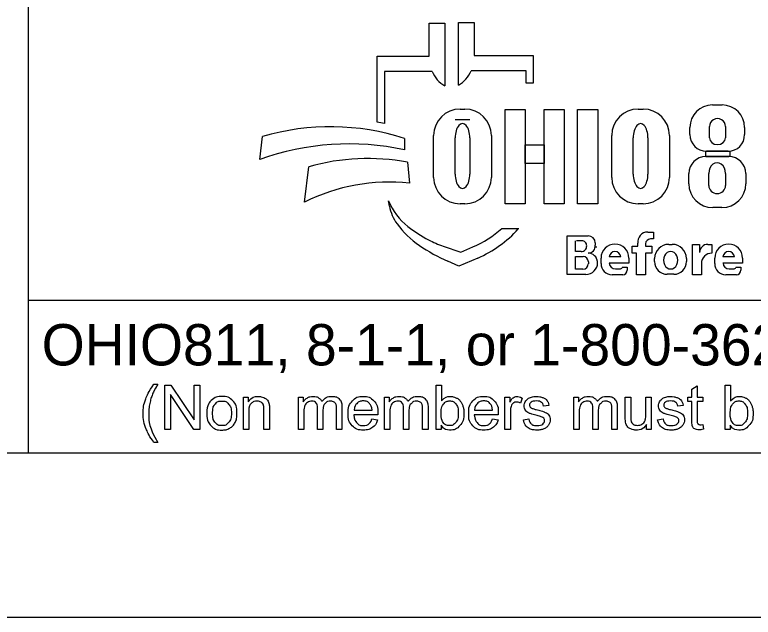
# Model space of a CAD drawing. Extents: x 0 to 34, y 0 to 22.
# Drawn here: x 2.043 to 4.294, y 0 to 1.837 of the extents above; entities that cross this region are included whole.
import ezdxf

# ---------------------------------------------------------------- set-up
doc = ezdxf.new("R2010")
doc.units = 0
for name, color, linetype in [('SH_Border', 7, 'Continuous'), ('SH_Cut_Line', 7, 'Continuous'), ('SH_Data', 7, 'Continuous'), ('SH_Text', 7, 'Continuous')]:
    doc.layers.add(name, color=color, linetype=linetype)

msp = doc.modelspace()

# ---------------------------------------------------------------- linework, layer by layer
at = {"layer": 'SH_Border'}
msp.add_lwpolyline([(1.5, 21.5), (33.5, 21.5), (33.5, 0.5), (1.5, 0.5)], close=True, dxfattribs=at)
at = {"layer": 'SH_Cut_Line'}
msp.add_lwpolyline([(0, 0), (34, 0), (34, 22), (0, 22)], close=True, dxfattribs=at)
at = {"layer": 'SH_Data'}
for p, q in [((2.0853, 0.5), (2.0853, 2.6037)), ((5.9103, 0.9661), (2.0853, 0.9661)), ((5.9103, 0.5), (2.0853, 0.5))]:
    msp.add_line(p, q, dxfattribs=at)
at = {"layer": 'SH_Text'}
for p, q in [((3.3057, 1.711), (3.3057, 1.8113)), ((3.3057, 1.8113), (3.354, 1.8113)), ((3.354, 1.8113), (3.354, 1.6204)), ((3.3951, 1.6225), (3.3951, 1.8134)), ((3.3951, 1.8134), (3.4433, 1.8134)), ((3.4433, 1.8134), (3.4433, 1.713)), ((3.1473, 1.5095), (3.1473, 1.711)), ((3.1473, 1.711), (3.3057, 1.711)), ((3.4433, 1.713), (3.6227, 1.713)), ((3.6227, 1.713), (3.6227, 1.6286)), ((3.6017, 1.6667), (3.434, 1.6667)), ((3.6017, 1.6286), (3.6017, 1.6667)), ((3.1701, 1.6647), (3.1701, 1.5055)), ((3.3151, 1.6647), (3.1701, 1.6647)), ((3.6227, 1.6286), (3.6017, 1.6286)), ((4.1693, 1.5623), (4.1988, 1.5623)), ((3.4002, 1.5497), (3.4151, 1.5497)), ((3.9429, 1.5497), (3.9578, 1.5497)), ((3.4301, 1.5164), (3.3853, 1.5164)), ((4.1006, 1.4717), (4.1006, 1.4936)), ((4.1602, 1.4615), (4.1602, 1.4969)), ((4.2089, 1.4969), (4.2089, 1.4615)), ((4.2675, 1.4936), (4.2675, 1.4717)), ((2.7897, 1.3958), (2.7982, 1.4661)), ((3.3197, 1.3414), (3.3197, 1.4692)), ((3.4956, 1.4692), (3.4956, 1.3414)), ((3.8624, 1.3414), (3.8624, 1.4692)), ((4.0383, 1.4692), (4.0383, 1.3414)), ((3.2313, 1.4603), (3.2313, 1.4253)), ((3.3853, 1.3516), (3.3853, 1.4617)), ((3.4301, 1.4617), (3.4301, 1.3516)), ((3.928, 1.3516), (3.928, 1.4617)), ((3.9728, 1.4617), (3.9728, 1.3516)), ((4.2171, 1.4213), (4.151, 1.4213)), ((4.1494, 1.4049), (4.219, 1.4049)), ((2.9264, 1.2657), (2.9396, 1.3738)), ((3.2403, 1.3877), (3.2459, 1.3239)), ((4.0973, 1.3221), (4.0973, 1.3528)), ((4.158, 1.3168), (4.158, 1.3536)), ((4.2092, 1.3536), (4.2092, 1.3168)), ((4.2711, 1.3528), (4.2711, 1.3221)), ((3.1853, 1.2541), (3.1825, 1.2702)), ((3.4151, 1.2608), (3.4002, 1.2608)), ((3.9578, 1.2608), (3.9429, 1.2608)), ((4.1982, 1.2493), (4.1702, 1.2493)), ((3.5275, 1.1858), (3.5792, 1.1858)), ((3.972, 1.1748), (3.9895, 1.1748)), ((3.9895, 1.1748), (3.9895, 1.1541)), ((3.7267, 1.0456), (3.7267, 1.1633)), ((3.7267, 1.1633), (3.7908, 1.1633)), ((3.7519, 1.1152), (3.7519, 1.1484)), ((3.7746, 1.1484), (3.7554, 1.1484)), ((3.9895, 1.1537), (3.9804, 1.1537)), ((3.3489, 1.1315), (3.4024, 1.113)), ((3.4024, 1.113), (3.4394, 1.1291)), ((3.8121, 1.1419), (3.8121, 1.1348)), ((3.9247, 1.1106), (3.9247, 1.1312)), ((3.9247, 1.1312), (3.9421, 1.1312)), ((3.9421, 1.1312), (3.9421, 1.1407)), ((3.9656, 1.1388), (3.9656, 1.1312)), ((3.9656, 1.1312), (3.985, 1.1312)), ((3.985, 1.1312), (3.985, 1.1106)), ((4.0361, 1.1372), (4.047, 1.1372)), ((4.1083, 1.0446), (4.1083, 1.137)), ((4.1083, 1.137), (4.1304, 1.137)), ((4.1304, 1.137), (4.1304, 1.1128)), ((4.155, 1.137), (4.1675, 1.137)), ((4.1675, 1.137), (4.1675, 1.1103)), ((3.7694, 1.1152), (3.7519, 1.1152)), ((3.9381, 1.1106), (3.9247, 1.1106)), ((3.9381, 1.0446), (3.9381, 1.1106)), ((3.985, 1.1106), (3.9656, 1.1106)), ((3.9656, 1.1106), (3.9656, 1.0446)), ((3.397, 1.0707), (3.3634, 1.0855)), ((3.454, 1.0954), (3.397, 1.0707)), ((3.7519, 1.0617), (3.7519, 1.1003)), ((3.7519, 1.1003), (3.7749, 1.1003)), ((3.7912, 1.0839), (3.7912, 1.0782)), ((3.8194, 1.0813), (3.8194, 1.081)), ((3.8298, 1.0787), (3.8298, 1.0953)), ((3.8897, 1.0989), (3.855, 1.0989)), ((3.9149, 1.0953), (3.9149, 1.0794)), ((3.9931, 1.0844), (3.9931, 1.0941)), ((4.0901, 1.0941), (4.0901, 1.0844)), ((4.1762, 1.0787), (4.1762, 1.0953)), ((4.2361, 1.0989), (4.2015, 1.0989)), ((4.2613, 1.0953), (4.2613, 1.0794)), ((3.7746, 1.0617), (3.7519, 1.0617)), ((3.9149, 1.0794), (3.8551, 1.0794)), ((3.8739, 1.0621), (3.8866, 1.0621)), ((3.8943, 1.0671), (3.9095, 1.0671)), ((3.9095, 1.0671), (3.9095, 1.0583)), ((4.1358, 1.0789), (4.1358, 1.0446)), ((4.2613, 1.0794), (4.2015, 1.0794)), ((4.2204, 1.0621), (4.2331, 1.0621)), ((4.2408, 1.0671), (4.256, 1.0671)), ((4.256, 1.0671), (4.256, 1.0583)), ((3.784, 1.0456), (3.7267, 1.0456)), ((3.8958, 1.0446), (3.864, 1.0446)), ((3.9656, 1.0446), (3.9381, 1.0446)), ((4.0516, 1.0459), (4.0316, 1.0459)), ((4.1358, 1.0446), (4.1083, 1.0446)), ((4.2423, 1.0446), (4.2104, 1.0446))]:
    msp.add_line(p, q, dxfattribs=at)
for points in [[(3.5374, 1.5487), (3.5985, 1.5487), (3.5985, 1.2608), (3.5374, 1.2608)], [(3.6563, 1.5487), (3.7175, 1.5487), (3.7175, 1.2608), (3.6563, 1.2608)], [(3.7583, 1.5487), (3.8202, 1.5487), (3.8202, 1.2608), (3.7583, 1.2608)], [(3.5985, 1.4408), (3.6563, 1.4408), (3.6563, 1.3833), (3.5985, 1.3833)], [(4.1491, 1.4214), (4.2226, 1.4214), (4.2226, 1.4047), (4.1491, 1.4047)]]:
    msp.add_lwpolyline(points, close=True, dxfattribs=at)
for points in [[(2.4674, 0.7104), (2.4793, 0.7104)], [(2.5005, 0.573), (2.5005, 0.7082), (2.5188, 0.7082), (2.5899, 0.602), (2.5899, 0.7082), (2.607, 0.7082), (2.607, 0.573), (2.5887, 0.573), (2.5176, 0.6792), (2.5176, 0.573), (2.5005, 0.573)], [(3.3424, 0.573), (3.3271, 0.573), (3.3271, 0.7082), (3.3436, 0.7082), (3.3436, 0.66)], [(4.1065, 0.6017), (4.1065, 0.6581), (4.0942, 0.6581), (4.0942, 0.671), (4.1065, 0.671), (4.1065, 0.6952), (4.123, 0.7052), (4.123, 0.671), (4.1396, 0.671), (4.1396, 0.6581), (4.123, 0.6581), (4.123, 0.6007)], [(4.2236, 0.573), (4.2082, 0.573), (4.2082, 0.7082), (4.2248, 0.7082), (4.2248, 0.66)], [(2.7399, 0.573), (2.7399, 0.671), (2.7548, 0.671), (2.7548, 0.6571)], [(2.9076, 0.573), (2.9076, 0.671), (2.9225, 0.671), (2.9225, 0.6571)], [(3.1699, 0.573), (3.1699, 0.671), (3.1847, 0.671), (3.1847, 0.6571)], [(3.5369, 0.573), (3.5369, 0.671), (3.5518, 0.671), (3.5518, 0.6561)], [(3.59, 0.6678), (3.5842, 0.6525)], [(3.7468, 0.573), (3.7468, 0.671), (3.7616, 0.671), (3.7616, 0.6571)], [(3.9037, 0.6103), (3.9037, 0.671), (3.9202, 0.671), (3.9202, 0.6167)], [(3.9664, 0.6185), (3.9664, 0.671), (3.983, 0.671), (3.983, 0.573), (3.9681, 0.573)], [(2.8194, 0.6332), (2.8194, 0.573), (2.8028, 0.573), (2.8028, 0.6325)], [(2.9824, 0.6299), (2.9824, 0.573), (2.9658, 0.573), (2.9658, 0.6366)], [(3.0404, 0.6402), (3.0404, 0.573), (3.0238, 0.573), (3.0238, 0.6347)], [(3.0774, 0.6313), (3.1321, 0.6313)], [(3.2446, 0.6299), (3.2446, 0.573), (3.2281, 0.573), (3.2281, 0.6366)], [(3.3026, 0.6402), (3.3026, 0.573), (3.2861, 0.573), (3.2861, 0.6347)], [(3.4446, 0.6313), (3.4993, 0.6313)], [(3.671, 0.6456), (3.6547, 0.6435)], [(3.8215, 0.6299), (3.8215, 0.573), (3.805, 0.573), (3.805, 0.6366)], [(3.8795, 0.6402), (3.8795, 0.573), (3.863, 0.573), (3.863, 0.6347)], [(4.0801, 0.6456), (4.0638, 0.6435)], [(2.7564, 0.6265), (2.7564, 0.573), (2.7399, 0.573)], [(2.9242, 0.6238), (2.9242, 0.573), (2.9076, 0.573)], [(3.1495, 0.6177), (3.0765, 0.6177)], [(3.1865, 0.6238), (3.1865, 0.573), (3.1699, 0.573)], [(3.5167, 0.6177), (3.4437, 0.6177)], [(3.5535, 0.6243), (3.5535, 0.573), (3.5369, 0.573)], [(3.7634, 0.6238), (3.7634, 0.573), (3.7468, 0.573)], [(3.1319, 0.6046), (3.149, 0.6025)], [(3.3424, 0.5853), (3.3424, 0.573)], [(3.4991, 0.6046), (3.5162, 0.6025)], [(3.5932, 0.6023), (3.6096, 0.6048)], [(3.9681, 0.573), (3.9681, 0.5875)], [(4.0023, 0.6023), (4.0187, 0.6048)], [(4.1396, 0.5878), (4.142, 0.5732)], [(4.2236, 0.5853), (4.2236, 0.573)], [(2.4793, 0.5333), (2.4674, 0.5333)]]:
    msp.add_lwpolyline(points, dxfattribs=at)
for centre, radius, start, end in [((3.3518, 1.6998), 0.0886, 299.2531, 338.0704), ((3.3973, 1.6978), 0.0886, 201.9296, 240.7469), ((4.1693, 1.4936), 0.0687, 90, 180), ((4.1988, 1.4936), 0.0687, 0, 90), ((3.4002, 1.4692), 0.0805, 90, 180), ((3.4151, 1.4692), 0.0805, 0, 90), ((3.9429, 1.4692), 0.0805, 90, 180), ((3.9578, 1.4692), 0.0805, 0, 90), ((3.032, 0.7814), 0.7372, 79.2074, 81.0007), ((3.0052, 0.7586), 0.7372, 72.1402, 106.3144), ((4.151, 1.4717), 0.0504, 180, 270), ((4.2171, 1.4717), 0.0504, 270, 0), ((3.062, 0.6406), 0.8027, 77.8238, 109.8274), ((3.1195, 0.7399), 0.659, 79.44, 105.8467), ((4.1494, 1.3528), 0.0521, 90, 180), ((4.219, 1.3528), 0.0521, 0, 90), ((3.4002, 1.3414), 0.0805, 180, 270), ((3.4151, 1.3414), 0.0805, 270, 0), ((3.9429, 1.3414), 0.0805, 180, 270), ((3.9578, 1.3414), 0.0805, 270, 0), ((3.1843, 0.755), 0.5721, 83.8248, 116.8021), ((4.1702, 1.3221), 0.0729, 180, 270), ((4.1982, 1.3221), 0.0729, 270, 0), ((3.3512, 1.3351), 0.1807, 201.0457, 232.5314), ((3.3124, 1.2758), 0.129, 189.6817, 216.0884), ((3.4328, 1.3635), 0.2779, 216.0884, 235.7167), ((3.5245, 1.5612), 0.4656, 232.5314, 241.794), ((3.3103, 1.4265), 0.3242, 293.4582, 312.0712), ((3.3103, 1.4265), 0.3609, 293.4582, 317.8286), ((3.972, 1.1446), 0.0302, 90, 187.5187), ((3.4478, 1.4183), 0.3034, 241.794, 250.9821), ((3.771, 1.1332), 0.0152, 357.8325, 90), ((3.7908, 1.1419), 0.0214, 0, 90), ((3.9804, 1.1388), 0.0148, 90, 180), ((3.5826, 1.5833), 0.5439, 235.7167, 246.2325), ((3.7694, 1.132), 0.0169, 270, 2.0582), ((3.7904, 1.1323), 0.0219, 270, 6.6529), ((3.7999, 1.1309), 0.0158, 347.4023, 0), ((3.8723, 1.0953), 0.0425, 0, 180), ((4.0361, 1.0941), 0.043, 90, 180), ((4.047, 1.0941), 0.043, 0, 90), ((4.1546, 1.1128), 0.0242, 89.2449, 180), ((4.2188, 1.0953), 0.0425, 0, 180), ((3.7905, 1.0815), 0.0289, 4.0748, 90), ((3.8724, 1.098), 0.0174, 2.9632, 177.0368), ((4.1672, 1.0789), 0.0314, 89.6033, 180), ((4.2188, 1.098), 0.0174, 2.9632, 177.0368), ((3.7749, 1.0839), 0.0163, 0, 90), ((3.784, 1.081), 0.0354, 270, 0), ((3.7897, 1.0813), 0.0297, 0, 11.7502), ((4.0316, 1.0844), 0.0385, 180, 270), ((4.0516, 1.0844), 0.0385, 270, 0), ((3.7746, 1.0782), 0.0165, 270, 0), ((3.864, 1.0787), 0.0342, 180, 270), ((3.8739, 1.081), 0.0189, 184.827, 270), ((3.8866, 1.0705), 0.00845, 270, 335.9979), ((3.8958, 1.0583), 0.0137, 270, 0), ((4.2104, 1.0787), 0.0342, 180, 270), ((4.2204, 1.081), 0.0189, 184.827, 270), ((4.2331, 1.0705), 0.00845, 270, 335.9979), ((4.2423, 1.0583), 0.0137, 270, 0)]:
    msp.add_arc(centre, radius, start, end, dxfattribs=at)
for centre, major_axis, ratio, start_param, end_param in [((4.1845, 1.4969), (0.0244, 0), 0.969373, 0, 3.141593), ((3.4077, 1.4617), (0, 0.0436), 0.514403, 4.712389, 7.853982), ((3.9504, 1.4617), (0, 0.0436), 0.514403, 4.712389, 7.853982), ((4.1845, 1.4615), (0.0244, 0), 0.818453, 3.141593, 6.283185), ((4.1836, 1.3536), (0, 0.0322), 0.794529, 4.712389, 7.853982), ((3.4077, 1.3516), (0, 0.0436), 0.514403, 1.570796, 4.712389), ((3.9504, 1.3516), (0, 0.0436), 0.514403, 1.570796, 4.712389), ((4.1836, 1.3168), (0.0256, 0), 0.959837, 3.141593, 6.283185), ((4.042, 1.0893), (0, 0.0261), 0.832186, 4.712389, 7.853982), ((4.042, 1.0893), (0, 0.0272), 0.797287, 1.570796, 4.712389)]:
    msp.add_ellipse(centre, major_axis=major_axis, ratio=ratio, start_param=start_param, end_param=end_param, dxfattribs=at)
for points in [[(2.4674, 0.5333), (2.4537, 0.5506), (2.4442, 0.5738), (2.4347, 0.597), (2.4347, 0.6219), (2.4347, 0.6439), (2.4418, 0.664), (2.4501, 0.6873), (2.4674, 0.7104)], [(2.4793, 0.7104), (2.4681, 0.6912), (2.4646, 0.683), (2.459, 0.6703), (2.4557, 0.6565), (2.4518, 0.6393), (2.4518, 0.6218), (2.4518, 0.5775), (2.4793, 0.5333)], [(2.6287, 0.622), (2.6287, 0.6492), (2.6438, 0.6623), (2.6565, 0.6731), (2.6746, 0.6731), (2.6948, 0.6731), (2.7076, 0.6599), (2.7204, 0.6467), (2.7204, 0.6234), (2.7204, 0.6045), (2.7147, 0.5937), (2.7091, 0.5828), (2.6982, 0.5768), (2.6874, 0.5709), (2.6746, 0.5709), (2.6541, 0.5709), (2.6414, 0.584), (2.6287, 0.5972), (2.6287, 0.622)], [(2.6458, 0.622), (2.6458, 0.6032), (2.654, 0.5938), (2.6622, 0.5845), (2.6746, 0.5845), (2.6869, 0.5845), (2.6951, 0.5939), (2.7033, 0.6033), (2.7033, 0.6225), (2.7033, 0.6407), (2.6951, 0.6501), (2.6868, 0.6594), (2.6746, 0.6594), (2.6622, 0.6594), (2.654, 0.6501), (2.6458, 0.6408), (2.6458, 0.622)], [(2.7548, 0.6571), (2.7656, 0.6731), (2.7859, 0.6731), (2.7948, 0.6731), (2.8022, 0.67), (2.8096, 0.6668), (2.8133, 0.6616), (2.817, 0.6564), (2.8185, 0.6493), (2.8194, 0.6447), (2.8194, 0.6332)], [(2.8028, 0.6325), (2.8028, 0.6427), (2.8009, 0.6477), (2.7989, 0.6527), (2.794, 0.6557), (2.7891, 0.6587), (2.7824, 0.6587), (2.7718, 0.6587), (2.7641, 0.652), (2.7564, 0.6453), (2.7564, 0.6265)], [(2.9225, 0.6571), (2.9271, 0.6644), (2.9347, 0.6687), (2.9424, 0.6731), (2.9522, 0.6731), (2.963, 0.6731), (2.97, 0.6686), (2.977, 0.6641), (2.9798, 0.6559), (2.9915, 0.6731), (3.0101, 0.6731), (3.0247, 0.6731), (3.0326, 0.6651), (3.0404, 0.657), (3.0404, 0.6402)], [(2.9658, 0.6366), (2.9658, 0.6477), (2.9618, 0.6532), (2.9577, 0.6587), (2.9485, 0.6587), (2.9415, 0.6587), (2.9355, 0.655), (2.9296, 0.6513), (2.9269, 0.6442), (2.9242, 0.6372), (2.9242, 0.6238)], [(3.0238, 0.6347), (3.0238, 0.6446), (3.0222, 0.649), (3.0206, 0.6534), (3.0163, 0.656), (3.0121, 0.6587), (3.0064, 0.6587), (2.9961, 0.6587), (2.9892, 0.6518), (2.9824, 0.645), (2.9824, 0.6299)], [(3.149, 0.6025), (3.145, 0.5874), (3.134, 0.5792), (3.1231, 0.5709), (3.106, 0.5709), (3.0845, 0.5709), (3.0719, 0.5841), (3.0594, 0.5973), (3.0594, 0.6212), (3.0594, 0.6459), (3.0721, 0.6595), (3.0848, 0.6731), (3.1051, 0.6731), (3.1247, 0.6731), (3.1372, 0.6598), (3.1496, 0.6464), (3.1496, 0.6221), (3.1496, 0.6207), (3.1495, 0.6177)], [(3.1321, 0.6313), (3.131, 0.6437), (3.1258, 0.6499), (3.1179, 0.6595), (3.1052, 0.6595), (3.0938, 0.6595), (3.086, 0.6519), (3.0782, 0.6442), (3.0774, 0.6313)], [(3.1847, 0.6571), (3.1893, 0.6644), (3.197, 0.6687), (3.2046, 0.6731), (3.2144, 0.6731), (3.2253, 0.6731), (3.2322, 0.6686), (3.2392, 0.6641), (3.2421, 0.6559), (3.2537, 0.6731), (3.2724, 0.6731), (3.2869, 0.6731), (3.2948, 0.6651), (3.3026, 0.657), (3.3026, 0.6402)], [(3.2281, 0.6366), (3.2281, 0.6477), (3.224, 0.6532), (3.2199, 0.6587), (3.2107, 0.6587), (3.2037, 0.6587), (3.1978, 0.655), (3.1918, 0.6513), (3.1891, 0.6442), (3.1865, 0.6372), (3.1865, 0.6238)], [(3.2861, 0.6347), (3.2861, 0.6446), (3.2844, 0.649), (3.2828, 0.6534), (3.2786, 0.656), (3.2743, 0.6587), (3.2686, 0.6587), (3.2583, 0.6587), (3.2515, 0.6518), (3.2446, 0.645), (3.2446, 0.6299)], [(3.3422, 0.6227), (3.3422, 0.6051), (3.347, 0.5973), (3.3548, 0.5845), (3.3682, 0.5845), (3.379, 0.5845), (3.3869, 0.5939), (3.3948, 0.6034), (3.3948, 0.6221), (3.3948, 0.6413), (3.3872, 0.6504), (3.3797, 0.6595), (3.3689, 0.6595), (3.358, 0.6595), (3.3501, 0.6501), (3.3422, 0.6406), (3.3422, 0.6227)], [(3.3436, 0.66), (3.3542, 0.6731), (3.3705, 0.6731), (3.3795, 0.6731), (3.3876, 0.6695), (3.3956, 0.6659), (3.4008, 0.6593), (3.406, 0.6527), (3.409, 0.6434), (3.4119, 0.6341), (3.4119, 0.6235), (3.4119, 0.5983), (3.3995, 0.5846), (3.387, 0.5709), (3.3696, 0.5709), (3.3523, 0.5709), (3.3424, 0.5853)], [(3.5162, 0.6025), (3.5122, 0.5874), (3.5012, 0.5792), (3.4902, 0.5709), (3.4732, 0.5709), (3.4517, 0.5709), (3.4391, 0.5841), (3.4266, 0.5973), (3.4266, 0.6212), (3.4266, 0.6459), (3.4393, 0.6595), (3.452, 0.6731), (3.4723, 0.6731), (3.4919, 0.6731), (3.5043, 0.6598), (3.5168, 0.6464), (3.5168, 0.6221), (3.5168, 0.6207), (3.5167, 0.6177)], [(3.4993, 0.6313), (3.4982, 0.6437), (3.493, 0.6499), (3.4851, 0.6595), (3.4724, 0.6595), (3.461, 0.6595), (3.4532, 0.6519), (3.4454, 0.6442), (3.4446, 0.6313)], [(3.5518, 0.6561), (3.5575, 0.6665), (3.5624, 0.6698), (3.5672, 0.6731), (3.573, 0.6731), (3.5814, 0.6731), (3.59, 0.6678)], [(3.5842, 0.6525), (3.5782, 0.656), (3.5721, 0.656), (3.5667, 0.656), (3.5624, 0.6528), (3.5581, 0.6495), (3.5562, 0.6437), (3.5535, 0.6348), (3.5535, 0.6243)], [(3.6547, 0.6435), (3.6536, 0.651), (3.6483, 0.6553), (3.643, 0.6595), (3.6333, 0.6595), (3.6218, 0.6595), (3.617, 0.6558), (3.6121, 0.652), (3.6121, 0.6469), (3.6121, 0.6437), (3.6141, 0.6411), (3.6161, 0.6384), (3.6205, 0.6366), (3.623, 0.6357), (3.6351, 0.6324), (3.6528, 0.6277), (3.6598, 0.6247), (3.6667, 0.6217), (3.6707, 0.616), (3.6747, 0.6103), (3.6747, 0.6018), (3.6747, 0.5935), (3.6698, 0.5862), (3.665, 0.5789), (3.6558, 0.5749), (3.6467, 0.5709), (3.6352, 0.5709), (3.616, 0.5709), (3.606, 0.5788), (3.596, 0.5867), (3.5932, 0.6023)], [(3.6096, 0.6048), (3.611, 0.595), (3.6173, 0.5897), (3.6236, 0.5845), (3.635, 0.5845), (3.6465, 0.5845), (3.652, 0.5891), (3.6576, 0.5938), (3.6576, 0.6001), (3.6576, 0.6057), (3.6527, 0.6089), (3.6493, 0.6111), (3.6357, 0.6146), (3.6174, 0.6192), (3.6104, 0.6225), (3.6033, 0.6259), (3.5996, 0.6318), (3.596, 0.6378), (3.596, 0.6449), (3.596, 0.6515), (3.599, 0.6571), (3.602, 0.6626), (3.6072, 0.6663), (3.611, 0.6692), (3.6177, 0.6712), (3.6244, 0.6731), (3.6321, 0.6731), (3.6436, 0.6731), (3.6524, 0.6698), (3.6611, 0.6665), (3.6653, 0.6608), (3.6694, 0.6551), (3.671, 0.6456)], [(3.7616, 0.6571), (3.7662, 0.6644), (3.7739, 0.6687), (3.7815, 0.6731), (3.7913, 0.6731), (3.8022, 0.6731), (3.8091, 0.6686), (3.8161, 0.6641), (3.819, 0.6559), (3.8306, 0.6731), (3.8492, 0.6731), (3.8638, 0.6731), (3.8717, 0.6651), (3.8795, 0.657), (3.8795, 0.6402)], [(3.805, 0.6366), (3.805, 0.6477), (3.8009, 0.6532), (3.7968, 0.6587), (3.7876, 0.6587), (3.7806, 0.6587), (3.7747, 0.655), (3.7687, 0.6513), (3.766, 0.6442), (3.7634, 0.6372), (3.7634, 0.6238)], [(3.863, 0.6347), (3.863, 0.6446), (3.8613, 0.649), (3.8597, 0.6534), (3.8555, 0.656), (3.8512, 0.6587), (3.8455, 0.6587), (3.8352, 0.6587), (3.8284, 0.6518), (3.8215, 0.645), (3.8215, 0.6299)], [(4.0638, 0.6435), (4.0627, 0.651), (4.0574, 0.6553), (4.0521, 0.6595), (4.0424, 0.6595), (4.031, 0.6595), (4.0261, 0.6558), (4.0212, 0.652), (4.0212, 0.6469), (4.0212, 0.6437), (4.0232, 0.6411), (4.0252, 0.6384), (4.0296, 0.6366), (4.0321, 0.6357), (4.0443, 0.6324), (4.0619, 0.6277), (4.0689, 0.6247), (4.0758, 0.6217), (4.0798, 0.616), (4.0838, 0.6103), (4.0838, 0.6018), (4.0838, 0.5935), (4.0789, 0.5862), (4.0741, 0.5789), (4.065, 0.5749), (4.0558, 0.5709), (4.0443, 0.5709), (4.0251, 0.5709), (4.0151, 0.5788), (4.0051, 0.5867), (4.0023, 0.6023)], [(4.0187, 0.6048), (4.0201, 0.595), (4.0264, 0.5897), (4.0328, 0.5845), (4.0441, 0.5845), (4.0556, 0.5845), (4.0612, 0.5891), (4.0667, 0.5938), (4.0667, 0.6001), (4.0667, 0.6057), (4.0618, 0.6089), (4.0584, 0.6111), (4.0448, 0.6146), (4.0265, 0.6192), (4.0195, 0.6225), (4.0124, 0.6259), (4.0088, 0.6318), (4.0051, 0.6378), (4.0051, 0.6449), (4.0051, 0.6515), (4.0081, 0.6571), (4.0111, 0.6626), (4.0163, 0.6663), (4.0202, 0.6692), (4.0269, 0.6712), (4.0336, 0.6731), (4.0412, 0.6731), (4.0528, 0.6731), (4.0615, 0.6698), (4.0702, 0.6665), (4.0744, 0.6608), (4.0785, 0.6551), (4.0801, 0.6456)], [(4.2234, 0.6227), (4.2234, 0.6051), (4.2281, 0.5973), (4.236, 0.5845), (4.2493, 0.5845), (4.2602, 0.5845), (4.2681, 0.5939), (4.276, 0.6034), (4.276, 0.6221), (4.276, 0.6413), (4.2684, 0.6504), (4.2608, 0.6595), (4.25, 0.6595), (4.2392, 0.6595), (4.2313, 0.6501), (4.2234, 0.6406), (4.2234, 0.6227)], [(4.2248, 0.66), (4.2353, 0.6731), (4.2516, 0.6731), (4.2607, 0.6731), (4.2687, 0.6695), (4.2768, 0.6659), (4.282, 0.6593), (4.2872, 0.6527), (4.2901, 0.6434), (4.2931, 0.6341), (4.2931, 0.6235), (4.2931, 0.5983), (4.2806, 0.5846), (4.2682, 0.5709), (4.2508, 0.5709), (4.2334, 0.5709), (4.2236, 0.5853)], [(3.0765, 0.6177), (3.0774, 0.6016), (3.0856, 0.593), (3.0938, 0.5845), (3.1061, 0.5845), (3.1152, 0.5845), (3.1217, 0.5893), (3.1281, 0.5941), (3.1319, 0.6046)], [(3.4437, 0.6177), (3.4446, 0.6016), (3.4528, 0.593), (3.461, 0.5845), (3.4733, 0.5845), (3.4824, 0.5845), (3.4889, 0.5893), (3.4953, 0.5941), (3.4991, 0.6046)], [(3.9681, 0.5875), (3.9567, 0.5709), (3.9371, 0.5709), (3.9284, 0.5709), (3.9209, 0.5742), (3.9134, 0.5775), (3.9098, 0.5825), (3.9061, 0.5875), (3.9047, 0.5948), (3.9037, 0.5997), (3.9037, 0.6103)], [(3.9202, 0.6167), (3.9202, 0.6037), (3.9213, 0.5992), (3.9228, 0.5926), (3.9279, 0.5889), (3.9329, 0.5852), (3.9404, 0.5852), (3.9479, 0.5852), (3.9544, 0.589), (3.9609, 0.5928), (3.9637, 0.5994), (3.9664, 0.606), (3.9664, 0.6185)], [(4.142, 0.5732), (4.135, 0.5717), (4.1295, 0.5717), (4.1205, 0.5717), (4.1155, 0.5745), (4.1105, 0.5774), (4.1085, 0.5821), (4.1065, 0.5867), (4.1065, 0.6017)], [(4.123, 0.6007), (4.123, 0.5936), (4.1239, 0.5916), (4.1248, 0.5895), (4.1268, 0.5883), (4.1287, 0.5871), (4.1324, 0.5871), (4.1351, 0.5871), (4.1396, 0.5878)]]:
    msp.add_open_spline(points, degree=3, dxfattribs=at)

# ---------------------------------------------------------------- texts
msp.add_text('OHIO811, 8-1-1, or 1-800-362-2764', height=0.126, dxfattribs=at).set_placement((2.1253, 0.768))

doc.saveas('drawing.dxf')
